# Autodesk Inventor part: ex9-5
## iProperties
Shininess: 64.0
Length Units: 11272
Angle Units: 11279
Time Units: 11290
Mass Units: 11286
Length Display Precision: 3
Angle Display Precision: 2
Compacted: True
Part Number: ex9-5
Document SubType Name: Sheet Metal
Created: 2002-11
Designer: Elise Moss
Density: 0.0
Volumn: 0.0
Area: 0.0
PropertySet Name: Model Information
Control State: 0
Master: False
Checked Out: False
Author: Elise Moss
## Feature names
1. Plate1
2. Bend1
3. Plate2
4. Bend2
5. Cut1
